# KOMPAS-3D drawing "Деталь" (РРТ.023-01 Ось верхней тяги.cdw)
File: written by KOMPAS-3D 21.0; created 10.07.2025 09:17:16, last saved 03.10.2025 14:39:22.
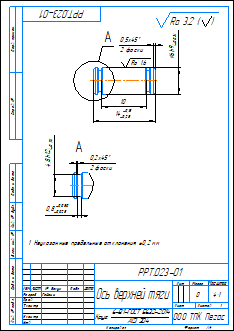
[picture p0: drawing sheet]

Sheet 1: A4, portrait

Document properties: Автор: User; Полное имя файла: C:\Users\User\Desktop\Ручной ротатор КД\Чертежи\РРТ.023-01 Ось верхней тяги.cdw; Знак неуказанной шероховатости: 4; Параметр неуказанной шероховатости: Ra 3.2; Масса: 0.002935

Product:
- Part/product: Деталь
    Масса: 0.002935
    Форматы листов документа: A4

Title block, sheet 1: Наименование: Ось верхней тяги; designation: РРТ.023 - 01; Материал: Круг  6-B1-ГОСТ 5632-2014 AISI 304; Масса: 0; Количество листов документа: 1; organisation: ООО ТПК Пегас; Форматы листов документа: A4; stored path: C:\Users\User\Desktop\Р-й Рот-р\Компас чертежи\Ось хомута ПРС.cdw; Разработал: Гайсин

Views: Вид 1, Слева, Выносной элемент 2, Выносной элемент А, Выносной элемент
Referenced files in C:\Users\User\Desktop\Ручной ротатор Ринат\П2\: Ось ПРС.m3d
Referenced files in C:\Users\User\Desktop\Ручной ротатор КД\Модели КД\: РРТ.023-01 Ось верхней тяги.m3d, РРТ.022 Ось ТЯГИ.m3d
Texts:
  Ra 1.6
  Ra 3.2
  Ra 3.2 ( )
Dimensions and other numbers on the sheet: 6; 14; 0,5; 2 фаски; 10; 0,8; 4,8; 0,2; 4:1; 1; 0

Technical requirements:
  Неуказанные предельные отклонения  0,2 мм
